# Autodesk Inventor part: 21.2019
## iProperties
Created: 2013-02
Part Number: 21.2019
Document SubType Name: Modeling
Designer: Administrator
Density: 7.85 g/cm^3
Material: Steel
Description: STOP FOR SLIDING DOOR
Vendor: S
Stock Number: 21.2019 STOP FOR SLIDING DOOR
Mass: 10.0853 g
Surface Area: 19.1479 cm^2
Volume: 1.28475 cm^3
Author: Administrator
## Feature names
1. Base1
